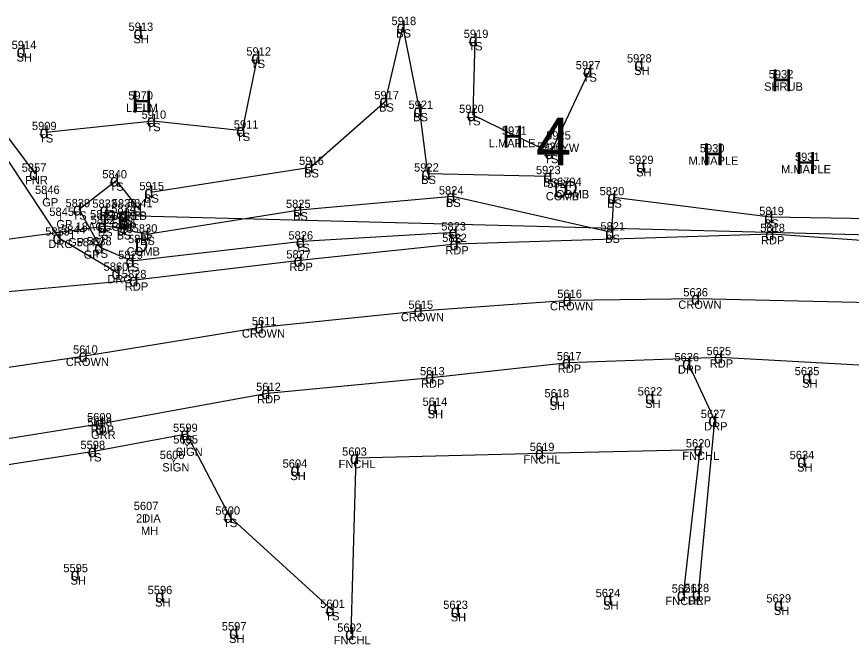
# Model space of a CAD drawing. Extents: x 69415 to 80913, y 7576 to 15059.
# Drawn here: x 74488.1 to 74689.4, y 14392.6 to 14543.9 of the extents above; entities that cross this region are included whole.
import ezdxf

# ---------------------------------------------------------------- set-up
doc = ezdxf.new("R2010")
doc.units = 0
for name, color, linetype in [('Level 11', 7, 'Continuous'), ('Level 12', 7, 'Continuous'), ('Level 14', 7, 'Continuous'), ('Level 15', 7, 'Continuous'), ('Level 43', 7, 'Continuous'), ('Level 46', 7, 'Continuous'), ('Level 47', 7, 'Continuous'), ('Level 48', 7, 'Continuous'), ('Level 59', 7, 'Continuous')]:
    doc.layers.add(name, color=color, linetype=linetype)

msp = doc.modelspace()

# ---------------------------------------------------------------- linework, layer by layer
at = {"layer": 'Level 11'}
for p, q in [((74484.83, 14511.07), (74498.29, 14490.59)), ((74670.09, 14491.46), (74593.98, 14489.06)), ((74708.4, 14488.75), (74670.09, 14491.46)), ((74498.29, 14490.59), (74512.5, 14482.11)), ((74593.98, 14489.06), (74556.4, 14485.08)), ((74556.4, 14485.08), (74516.74, 14480.33)), ((74516.74, 14480.33), (74478.86, 14476.85)), ((74621.09, 14460.53), (74657.73, 14461.76)), ((74657.73, 14461.76), (74697.56, 14459.57)), ((74588.12, 14456.91), (74621.09, 14460.53)), ((74650.06, 14460.3), (74656.37, 14446.61)), ((74548.61, 14453.14), (74588.12, 14456.91)), ((74508.5, 14445.83), (74548.61, 14453.14)), ((74656.37, 14446.61), (74652.43, 14404.64)), ((74461.84, 14438.29), (74508.5, 14445.83))]:
    msp.add_line(p, q, dxfattribs=at)
at = {"layer": 'Level 12'}
for p, q in [((74468.56, 14537.86), (74492.62, 14505.98)), ((74569.99, 14437.53), (74614.58, 14438.65)), ((74614.58, 14438.65), (74652.84, 14439.52)), ((74652.84, 14439.52), (74648.8, 14404.51)), ((74568.81, 14395.09), (74569.99, 14437.53))]:
    msp.add_line(p, q, dxfattribs=at)
at = {"layer": 'Level 48'}
for p, q in [((74577.06, 14523.48), (74581.2, 14541.34)), ((74581.2, 14541.34), (74585.28, 14521.15)), ((74598.61, 14538.24), (74598.14, 14520.17)), ((74542.6, 14516.4), (74546.2, 14534)), ((74616.91, 14511.04), (74626.18, 14530.7)), ((74558.98, 14507.62), (74577.06, 14523.48)), ((74585.28, 14521.15), (74587.21, 14506.03)), ((74598.14, 14520.17), (74616.91, 14511.04)), ((74495.15, 14516.04), (74521.02, 14518.76)), ((74521.02, 14518.76), (74542.6, 14516.4)), ((74520.4, 14501.55), (74558.98, 14507.62)), ((74587.21, 14506.03), (74616.59, 14505.41)), ((74503.17, 14497.44), (74512.13, 14504.4)), ((74512.13, 14504.4), (74517.66, 14497.41)), ((74593.18, 14500.5), (74556.32, 14497.26)), ((74631.55, 14491.83), (74593.18, 14500.5)), ((74632.02, 14500.32), (74631.55, 14491.83)), ((74669.85, 14495.53), (74632.02, 14500.32)), ((74508.34, 14488.24), (74503.17, 14497.44)), ((74509.25, 14493.41), (74509.64, 14497.31)), ((74509.64, 14497.31), (74514.19, 14496.11)), ((74556.32, 14497.26), (74519.44, 14491.33)), ((74514.19, 14496.11), (74514.29, 14494.33)), ((74711.85, 14494.84), (74669.85, 14495.53)), ((74513.79, 14492.64), (74509.25, 14493.41)), ((74519.44, 14491.33), (74513.79, 14492.64)), ((74593.76, 14491.83), (74556.97, 14489.65)), ((74556.97, 14489.65), (74515.87, 14484.93)), ((74515.87, 14484.93), (74508.34, 14488.24)), ((74585.32, 14472.94), (74621.26, 14475.56)), ((74621.26, 14475.56), (74652.2, 14475.94)), ((74652.2, 14475.94), (74699.18, 14474.87)), ((74547, 14468.99), (74585.32, 14472.94)), ((74504.56, 14462.14), (74547, 14468.99)), ((74457.99, 14455.13), (74504.56, 14462.14)), ((74506.78, 14439.14), (74529.1, 14443.27)), ((74529.1, 14443.27), (74539.51, 14423.31)), ((74462.56, 14432.3), (74506.78, 14439.14)), ((74539.51, 14423.31), (74564.12, 14400.84))]:
    msp.add_line(p, q, dxfattribs=at)
at = {"layer": 'Level 59'}
for p, q in [((74835.26, 14487.5), (74514.39, 14495.88)), ((74509.09, 14493.26), (74469.33, 14487.92))]:
    msp.add_line(p, q, dxfattribs=at)

# ---------------------------------------------------------------- texts
at = {"layer": 'Level 12'}
for p in [(74495.02, 14499.78), (74498.42, 14494.5), (74501.26, 14490.18), (74505, 14487.17)]:
    msp.add_text('I', height=1.7, dxfattribs=at).set_placement(p)
at = {"layer": 'Level 14'}
for p in [(74670.05, 14525.87), (74515.75, 14520.73), (74605.17, 14512.26), (74653.53, 14508.01), (74675.83, 14505.95)]:
    msp.add_text('H', height=5.3, dxfattribs=at).set_placement(p)
at = {"layer": 'Level 15'}
for s, height, p in [('4', 11.5, (74613.29, 14508)), ('D', 3.4, (74617.62, 14500.39)), ('D', 3.4, (74620.07, 14500.88)), ('D', 3.4, (74516.56, 14487.09)), ('I', 1.7, (74518.89, 14422.07))]:
    msp.add_text(s, height=height, dxfattribs=at).set_placement(p)
at = {"layer": 'Level 43'}
for p in [(74528.44, 14439.61), (74525.23, 14435.88)]:
    msp.add_text('Y', height=1.7, dxfattribs=at).set_placement(p)
at = {"layer": 'Level 46'}
for s, p in [('5918', (74578.5, 14541.84)), ('5913', (74515.11, 14540.46)), ('SH', (74516.29, 14537.46)), ('BS', (74579.64, 14538.84)), ('5919', (74595.91, 14538.74)), ('5914', (74486.93, 14536.06)), ('TS', (74597.02, 14535.74)), ('SH', (74488.11, 14533.06)), ('5912', (74543.51, 14534.5)), ('TS', (74544.61, 14531.5)), ('5927', (74622.92, 14531.2)), ('5928', (74635.27, 14532.83)), ('SH', (74637.01, 14529.83)), ('5932', (74669.44, 14529.02)), ('TS', (74624.59, 14528.2)), ('SHRUB', (74668.33, 14526.02)), ('5970', (74515.05, 14523.88)), ('5917', (74574.36, 14523.98)), ('BS', (74575.5, 14520.98)), ('5921', (74582.59, 14521.65)), ('L.ELM', (74514.48, 14520.88)), ('5910', (74518.24, 14519.26)), ('5920', (74594.8, 14520.67)), ('5911', (74540.48, 14516.9)), ('BS', (74583.72, 14518.65)), ('TS', (74596.55, 14517.67)), ('5909', (74491.81, 14516.54)), ('TS', (74519.43, 14516.26)), ('5971', (74605.13, 14515.41)), ('TS', (74493.56, 14513.54)), ('TS', (74541.01, 14513.9)), ('5925', (74615.78, 14514.25)), ('L.MAPLE', (74601.93, 14512.41)), ('5926', (74613.59, 14511.54)), ('GUYW', (74615.44, 14511.25)), ('5930', (74652.83, 14511.16)), ('5931', (74675.78, 14509.1)), ('5916', (74556.23, 14508.12)), ('TS', (74615.32, 14508.54)), ('5929', (74635.72, 14508.36)), ('M.MAPLE', (74650.12, 14508.16)), ('5857', (74489.36, 14506.48)), ('5840', (74508.79, 14504.9)), ('BS', (74557.42, 14505.12)), ('5922', (74583.95, 14506.53)), ('5923', (74613.33, 14505.91)), ('SH', (74637.48, 14505.36)), ('M.MAPLE', (74672.41, 14506.1)), ('FNR', (74490.16, 14503.48)), ('BS', (74585.65, 14503.53)), ('BS', (74615.03, 14502.91)), ('6704', (74618.38, 14503.08)), ('5846', (74492.56, 14501.13)), ('TS', (74510.54, 14501.9)), ('5915', (74517.71, 14502.05)), ('5824', (74589.92, 14501)), ('5924', (74616.06, 14502.59)), ('5820', (74628.67, 14500.82)), ('BS', (74518.84, 14499.05)), ('COMB', (74615.7, 14499.59)), ('COMB', (74618.15, 14500.08)), ('GP', (74494.3, 14498.13)), ('5839', (74499.91, 14497.94)), ('5833', (74506.38, 14497.81)), ('5836', (74511.07, 14497.88)), ('5841', (74514.96, 14497.91)), ('5825', (74553.06, 14497.76)), ('BS', (74591.62, 14498)), ('BS', (74630.46, 14497.82)), ('5845', (74496.01, 14495.85)), ('TS', (74501.58, 14494.94)), ('5842', (74505.83, 14495.26)), ('BS', (74508.08, 14494.81)), ('24CPEP', (74509.18, 14494.88)), ('5834', (74510.93, 14496.61)), ('5835', (74511.03, 14494.83)), ('TS', (74516.07, 14494.91)), ('BS', (74554.77, 14494.76)), ('5819', (74667.15, 14496.03)), ('GP', (74497.71, 14492.85)), ('5832', (74505.99, 14493.91)), ('5831', (74511.1, 14493.14)), ('BS', (74512.63, 14493.61)), ('BS', (74668.29, 14493.03)), ('5859', (74495.02, 14491.09)), ('5844', (74498.85, 14491.53)), ('18ACCGMP', (74502.35, 14492.26)), ('BS', (74507.69, 14490.91)), ('BS', (74512.73, 14491.83)), ('P', (74513.76, 14491.88)), ('5830', (74516.1, 14491.83)), ('5823', (74590.5, 14492.33)), ('5821', (74628.86, 14492.33)), ('5818', (74667.39, 14491.96)), ('5838', (74505.08, 14488.74)), ('P', (74508.47, 14489.26)), ('BS', (74512.23, 14490.14)), ('5837', (74515, 14489.29)), ('BS', (74517.88, 14488.83)), ('5826', (74553.65, 14490.15)), ('5822', (74590.72, 14489.56)), ('TS', (74592.17, 14489.33)), ('BS', (74629.99, 14489.33)), ('RDP', (74667.57, 14488.96)), ('DRG', (74495.78, 14488.09)), ('GP', (74500.54, 14488.53)), ('5843', (74502.59, 14488.52)), ('TS', (74555.38, 14487.15)), ('GP', (74504.28, 14485.52)), ('TS', (74506.75, 14485.74)), ('5829', (74512.6, 14485.43)), ('COMB', (74514.65, 14486.29)), ('5827', (74553.14, 14485.58)), ('RDP', (74591.47, 14486.56)), ('5860', (74509.1, 14482.61)), ('5828', (74513.48, 14480.83)), ('TS', (74514.28, 14482.43)), ('RDP', (74553.89, 14482.58)), ('DRG', (74509.99, 14479.61)), ('RDP', (74514.22, 14477.83)), ('5616', (74618.47, 14476.06)), ('5636', (74648.84, 14476.44)), ('5615', (74582.58, 14473.44)), ('CROWN', (74616.71, 14473.06)), ('CROWN', (74647.64, 14473.44)), ('5611', (74544.83, 14469.49)), ('CROWN', (74580.76, 14470.44)), ('CROWN', (74542.44, 14466.49)), ('5610', (74501.73, 14462.64)), ('5617', (74618.35, 14461.03)), ('5626', (74646.7, 14460.8)), ('5625', (74654.43, 14462.26)), ('CROWN', (74500, 14459.64)), ('RDP', (74655.22, 14459.26)), ('5613', (74585.38, 14457.41)), ('RDP', (74618.58, 14458.03)), ('DRP', (74647.55, 14457.8)), ('5635', (74675.7, 14457.43)), ('5612', (74545.87, 14453.64)), ('RDP', (74585.61, 14454.41)), ('5622', (74637.85, 14452.54)), ('SH', (74677.5, 14454.43)), ('RDP', (74546.1, 14450.64)), ('5618', (74615.38, 14452.09)), ('5614', (74585.99, 14450.05)), ('SH', (74616.61, 14449.09)), ('SH', (74639.64, 14449.54)), ('SH', (74587.22, 14447.05)), ('5627', (74653.06, 14447.11)), ('5609', (74505.1, 14446.33)), ('5608', (74505.19, 14445.08)), ('RDP', (74505.98, 14443.33)), ('5599', (74525.83, 14443.77)), ('DRP', (74653.86, 14444.11)), ('GRR', (74506.06, 14442.08)), ('5605', (74525.91, 14440.96)), ('TS', (74527.51, 14440.77)), ('5598', (74503.52, 14439.64)), ('5619', (74611.83, 14439.15)), ('5620', (74649.45, 14440.02)), ('TS', (74505.19, 14436.64)), ('5606', (74522.64, 14437.23)), ('SIGN', (74526.45, 14437.96)), ('5603', (74566.6, 14438.03)), ('FNCHL', (74648.59, 14437.02)), ('5634', (74674.48, 14437.2)), ('5604', (74552.25, 14435.14)), ('FNCHL', (74565.74, 14435.03)), ('FNCHL', (74610.33, 14436.15)), ('SIGN', (74523.24, 14434.23)), ('SH', (74676.28, 14434.2)), ('SH', (74554.12, 14432.14)), ('5607', (74516.36, 14424.92)), ('5600', (74536.04, 14423.81)), ('2DIA', (74516.92, 14421.92)), ('TS', (74537.92, 14420.81)), ('MH', (74518.1, 14418.92)), ('5595', (74499.38, 14409.95)), ('SH', (74501.13, 14406.95)), ('5596', (74519.71, 14404.66)), ('5621', (74646.06, 14405.01)), ('5628', (74649.13, 14405.14)), ('5624', (74627.72, 14403.93)), ('5629', (74668.88, 14402.64)), ('SH', (74521.51, 14401.66)), ('5601', (74561.31, 14401.34)), ('5623', (74590.97, 14401.09)), ('SH', (74629.52, 14400.93)), ('FNCHL', (74644.55, 14402.01)), ('DRP', (74649.92, 14402.14)), ('TS', (74562.53, 14398.34)), ('SH', (74670.68, 14399.64)), ('SH', (74592.77, 14398.09)), ('5597', (74537.59, 14395.9)), ('5602', (74565.42, 14395.59)), ('SH', (74539.34, 14392.9)), ('FNCHL', (74564.56, 14392.59))]:
    msp.add_text(s, height=2, dxfattribs=at).set_placement(p)
at = {"layer": 'Level 47'}
for p in [(74516.3, 14538.46), (74579.7, 14539.84), (74597.11, 14536.74), (74488.12, 14534.06), (74544.7, 14532.5), (74637.03, 14530.83), (74624.68, 14529.2), (74575.56, 14521.98), (74583.78, 14519.65), (74596.64, 14518.67), (74519.52, 14517.26), (74493.65, 14514.54), (74541.1, 14514.9), (74615.41, 14509.54), (74557.48, 14506.12), (74637.49, 14506.36), (74491.12, 14504.48), (74585.71, 14504.53), (74615.09, 14503.91), (74510.63, 14502.9), (74518.9, 14500.05), (74591.68, 14499), (74630.52, 14498.82), (74501.67, 14495.94), (74508.14, 14495.81), (74516.16, 14495.91), (74554.82, 14495.76), (74512.69, 14494.61), (74512.89, 14494.38), (74668.35, 14494.03), (74507.59, 14491.76), (74507.75, 14491.91), (74512.79, 14492.83), (74512.29, 14491.14), (74517.94, 14489.83), (74592.26, 14490.33), (74630.05, 14490.33), (74668.59, 14489.96), (74496.79, 14489.09), (74555.47, 14488.15), (74592.48, 14487.56), (74506.84, 14486.74), (74554.9, 14483.58), (74514.37, 14483.43), (74511, 14480.61), (74515.24, 14478.83), (74619.76, 14474.06), (74650.7, 14474.44), (74583.82, 14471.44), (74545.5, 14467.49), (74503.06, 14460.64), (74656.23, 14460.26), (74619.59, 14459.03), (74648.56, 14458.8), (74586.62, 14455.41), (74677.51, 14455.43), (74547.11, 14451.64), (74616.62, 14450.09), (74639.65, 14450.54), (74587.23, 14448.05), (74507, 14444.33), (74654.87, 14445.11), (74507.07, 14443.08), (74527.6, 14441.77), (74505.28, 14437.64), (74651.34, 14438.02), (74568.49, 14436.03), (74613.08, 14437.15), (74676.29, 14435.2), (74554.13, 14433.14), (74538.01, 14421.81), (74501.14, 14407.95), (74650.93, 14403.14), (74521.53, 14402.66), (74629.53, 14401.93), (74647.3, 14403.01), (74562.62, 14399.34), (74592.78, 14399.09), (74670.69, 14400.64), (74539.35, 14393.9), (74567.31, 14393.59)]:
    msp.add_text('d', height=3, dxfattribs=at).set_placement(p)

doc.saveas('drawing.dxf')
